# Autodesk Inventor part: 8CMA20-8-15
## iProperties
Created: 2009-08
Part Number: 8CMA20-8-15
Document SubType Name: Modeling
Designer: Darius
Author: Darius
Translation Standard: STEP AP203
File Name: 8CMA20-8-15.STEP
Preprocessor: SolidWorks 2003240
Postprocessor: Build: 272, Release: 10 SP3a - Date: Thu 12/15/2005
Sent Units: MILLIMETERS
Uncertainty: 1e-05
